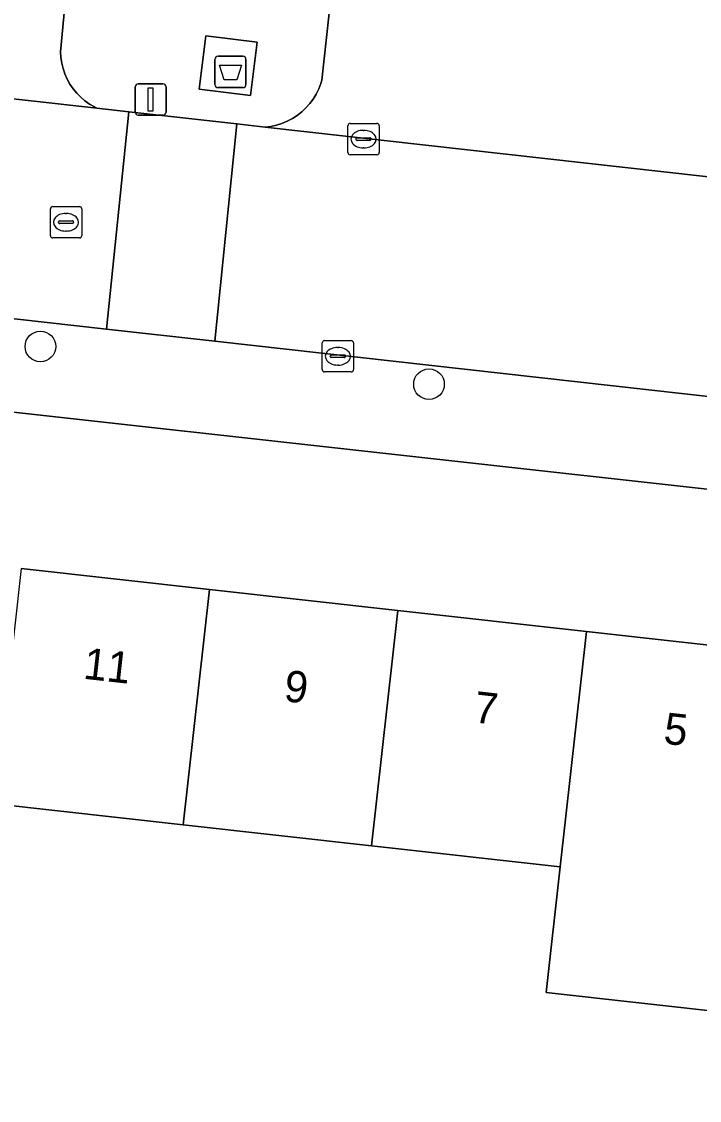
# Model space of a CAD drawing. Extents: x 161928 to 163071, y 386474 to 387428.
# Drawn here: x 162343.49 to 162365.12, y 386624.08 to 386658.51 of the extents above; entities that cross this region are included whole.
import ezdxf

# ---------------------------------------------------------------- set-up
doc = ezdxf.new("R2010")
doc.units = 0
for name, color, linetype in [('IMGEO_Afval_apart_plaats', 7, 'Continuous'), ('IMGEO_Boom', 7, 'Continuous'), ('IMGEO_Erf', 7, 'Continuous'), ('IMGEO_Kolk', 7, 'Continuous'), ('IMGEO_Lichtmast', 7, 'Continuous'), ('IMGEO_Pand', 7, 'Continuous'), ('IMGEO_Pand_nummerreeks', 7, 'Continuous'), ('IMGEO_Parkeervlak_open', 7, 'Continuous'), ('IMGEO_Rijbaan_lokaal_open', 7, 'Continuous'), ('IMGEO_Rioolput', 7, 'Continuous'), ('IMGEO_Voetpad_gesloten', 7, 'Continuous'), ('IMGEO_Voetpad_open', 7, 'Continuous')]:
    doc.layers.add(name, color=color, linetype=linetype)

msp = doc.modelspace()

# ---------------------------------------------------------------- linework, layer by layer
at = {"layer": 'IMGEO_Afval_apart_plaats'}
for p, q in [((162349.765, 386657.407), (162350.555, 386657.407)), ((162350.555, 386657.407), (162349.765, 386657.407)), ((162349.665, 386656.507), (162349.665, 386657.307)), ((162349.665, 386657.307), (162349.665, 386656.507)), ((162350.655, 386657.307), (162350.655, 386656.507)), ((162350.655, 386656.507), (162350.655, 386657.307)), ((162350.555, 386656.407), (162349.765, 386656.407)), ((162349.765, 386656.407), (162350.555, 386656.407))]:
    msp.add_line(p, q, dxfattribs=at)
msp.add_lwpolyline([(162349.808, 386657.121), (162350.512, 386657.121), (162350.363, 386656.651), (162349.957, 386656.651), (162349.808, 386657.121)], dxfattribs=at)
for centre, start, end in [((162349.765, 386657.307), 90, 180), ((162349.765, 386657.307), 90, 180), ((162350.555, 386657.307), 0, 90), ((162350.555, 386657.307), 360, 90), ((162349.765, 386656.507), 180, 270), ((162349.765, 386656.507), 180, 270), ((162350.555, 386656.507), 270, 0), ((162350.555, 386656.507), 270, 0)]:
    msp.add_arc(centre, 0.1, start, end, dxfattribs=at)
at = {"layer": 'IMGEO_Boom'}
for centre in [(162344.095, 386648.145), (162356.495, 386646.941)]:
    msp.add_circle(centre, 0.489, dxfattribs=at)
at = {"layer": 'IMGEO_Erf'}
for points in [[(162380.485, 386616.728), (162382.904, 386638.649), (162382.921, 386638.915), (162382.915, 386639.182), (162382.885, 386639.447), (162382.831, 386639.709), (162382.754, 386639.964), (162382.654, 386640.212), (162382.533, 386640.45), (162382.391, 386640.676), (162382.229, 386640.888), (162382.049, 386641.085), (162381.852, 386641.266), (162381.64, 386641.427), (162381.414, 386641.57), (162381.177, 386641.691), (162380.929, 386641.791), (162380.674, 386641.869), (162380.412, 386641.923), (162215.989, 386660.188)], [(162343.479, 386641.063), (162349.492, 386640.391), (162355.505, 386639.719), (162361.517, 386639.048), (162367.53, 386638.376), (162373.542, 386637.704), (162379.735, 386637.012), (162378.895, 386629.497), (162373.926, 386630.052), (162372.702, 386630.186), (162366.69, 386630.859), (162366.243, 386626.856), (162360.23, 386627.527), (162360.677, 386631.533), (162354.665, 386632.205), (162348.652, 386632.877), (162342.639, 386633.548)]]:
    msp.add_lwpolyline(points, dxfattribs=at)
at = {"layer": 'IMGEO_Kolk'}
for p, q in [((162353.981, 386655.263), (162354.833, 386655.263)), ((162353.906, 386654.337), (162353.906, 386655.189)), ((162354.394, 386655.043), (162354.419, 386655.043)), ((162354.907, 386655.189), (162354.907, 386654.337)), ((162354.165, 386654.757), (162354.165, 386654.769)), ((162354.603, 386654.72), (162354.205, 386654.72)), ((162354.208, 386654.806), (162354.606, 386654.806)), ((162354.649, 386654.769), (162354.649, 386654.757)), ((162354.833, 386654.263), (162353.981, 386654.263)), ((162354.417, 386654.483), (162354.392, 386654.483)), ((162353.087, 386647.405), (162353.087, 386648.257)), ((162353.162, 386648.331), (162354.014, 386648.331)), ((162353.575, 386648.111), (162353.6, 386648.111)), ((162354.088, 386648.257), (162354.088, 386647.405)), ((162353.346, 386647.825), (162353.346, 386647.837)), ((162353.784, 386647.788), (162353.386, 386647.788)), ((162353.389, 386647.874), (162353.787, 386647.874)), ((162353.83, 386647.837), (162353.83, 386647.825)), ((162353.598, 386647.551), (162353.573, 386647.551)), ((162354.014, 386647.331), (162353.162, 386647.331))]:
    msp.add_line(p, q, dxfattribs=at)
for points in [[(162353.981, 386655.263), (162354.833, 386655.263)], [(162353.906, 386654.337), (162353.906, 386655.189)], [(162354.907, 386655.189), (162354.907, 386654.337)], [(162354.833, 386654.263), (162353.981, 386654.263)], [(162353.087, 386647.405), (162353.087, 386648.257)], [(162353.162, 386648.331), (162354.014, 386648.331)], [(162354.088, 386648.257), (162354.088, 386647.405)], [(162354.014, 386647.331), (162353.162, 386647.331)]]:
    msp.add_lwpolyline(points, dxfattribs=at)
for centre, radius, start, end in [((162353.983, 386655.187), 0.0765, 91.552, 178.448), ((162353.983, 386655.187), 0.0765, 91.552, 178.448), ((162354.831, 386655.187), 0.0765, 1.552, 88.448), ((162354.831, 386655.187), 0.0765, 1.552, 88.448), ((162354.205, 386654.766), 0.0403, 85.8775, 175.7526), ((162354.202, 386654.756), 0.0366, 178.938, 274.7102), ((162354.606, 386654.763), 0.043, 264.8664, 352.4533), ((162354.61, 386654.768), 0.0386, 1.7309, 96.639), ((162353.983, 386654.339), 0.0765, 181.552, 268.448), ((162353.983, 386654.339), 0.0765, 181.552, 268.448), ((162354.831, 386654.339), 0.0765, 271.552, 358.448), ((162354.831, 386654.339), 0.0765, 271.552, 358.448), ((162353.164, 386648.255), 0.0765, 91.552, 178.448), ((162353.164, 386648.255), 0.0765, 91.552, 178.448), ((162354.012, 386648.255), 0.0765, 1.552, 88.448), ((162354.012, 386648.255), 0.0765, 1.552, 88.448), ((162353.386, 386647.834), 0.0403, 85.8775, 175.7526), ((162353.383, 386647.824), 0.0366, 178.938, 274.7102), ((162353.787, 386647.831), 0.043, 264.8664, 352.4533), ((162353.791, 386647.836), 0.0386, 1.7309, 96.639), ((162353.164, 386647.407), 0.0765, 181.552, 268.448), ((162353.164, 386647.407), 0.0765, 181.552, 268.448), ((162354.012, 386647.407), 0.0765, 271.552, 358.448), ((162354.012, 386647.407), 0.0765, 271.552, 358.448)]:
    msp.add_arc(centre, radius, start, end, dxfattribs=at)
for centre, major_axis, ratio, start_param, end_param in [((162354.393, 386654.763), (-0.387, 0.002), 0.722429, 4.712389, 7.853982), ((162354.418, 386654.763), (-0.39, 0.002), 0.717154, 1.570796, 4.712389), ((162353.574, 386647.831), (-0.387, 0.002), 0.722429, 4.712389, 7.853982), ((162353.599, 386647.831), (-0.39, 0.002), 0.717154, 1.570796, 4.712389)]:
    msp.add_ellipse(centre, major_axis=major_axis, ratio=ratio, start_param=start_param, end_param=end_param, dxfattribs=at)
at = {"layer": 'IMGEO_Lichtmast'}
for p, q in [((162347.117, 386655.628), (162347.117, 386656.428)), ((162347.117, 386656.428), (162347.117, 386655.628)), ((162347.217, 386656.528), (162348.007, 386656.528)), ((162348.007, 386656.528), (162347.217, 386656.528)), ((162348.107, 386656.428), (162348.107, 386655.628)), ((162348.107, 386655.628), (162348.107, 386656.428)), ((162348.007, 386655.528), (162347.217, 386655.528)), ((162347.217, 386655.528), (162348.007, 386655.528))]:
    msp.add_line(p, q, dxfattribs=at)
msp.add_lwpolyline([(162347.537, 386656.403), (162347.687, 386656.403), (162347.687, 386655.653), (162347.537, 386655.653), (162347.537, 386656.403)], dxfattribs=at)
for centre, start, end in [((162347.217, 386656.428), 90, 180), ((162347.217, 386656.428), 90, 180), ((162348.007, 386656.428), 0, 90), ((162348.007, 386656.428), 360, 90), ((162347.217, 386655.628), 180, 270), ((162347.217, 386655.628), 180, 270), ((162348.007, 386655.628), 270, 0), ((162348.007, 386655.628), 270, 0)]:
    msp.add_arc(centre, 0.1, start, end, dxfattribs=at)
at = {"layer": 'IMGEO_Pand'}
for points in [[(162349.492, 386640.391), (162343.479, 386641.063), (162342.639, 386633.548), (162348.652, 386632.877)], [(162348.652, 386632.877), (162354.665, 386632.205), (162355.505, 386639.719), (162349.492, 386640.391)], [(162354.665, 386632.205), (162360.677, 386631.533), (162361.517, 386639.048), (162355.505, 386639.719)], [(162367.53, 386638.376), (162361.517, 386639.048), (162360.677, 386631.533), (162360.23, 386627.527), (162366.243, 386626.856), (162366.69, 386630.859)]]:
    msp.add_lwpolyline(points, close=True, dxfattribs=at)
at = {"layer": 'IMGEO_Parkeervlak_open'}
for points in [[(162308.731, 386659.914), (162345.899, 386655.749), (162345.821, 386655.788), (162345.665, 386655.879), (162345.517, 386655.983), (162345.38, 386656.101), (162345.253, 386656.23), (162345.139, 386656.37), (162345.037, 386656.52), (162344.949, 386656.678), (162344.876, 386656.843), (162344.817, 386657.015), (162344.775, 386657.19), (162344.748, 386657.369), (162344.737, 386657.55), (162345.039, 386660.716)], [(162353.45, 386660.059), (162353.075, 386656.639), (162353.042, 386656.533), (162352.976, 386656.363), (162352.895, 386656.198), (162352.799, 386656.042), (162352.69, 386655.895), (162352.568, 386655.758), (162352.434, 386655.632), (162352.289, 386655.519), (162352.135, 386655.42), (162351.973, 386655.334), (162351.804, 386655.264), (162351.629, 386655.209), (162351.45, 386655.169), (162351.268, 386655.146), (162380.511, 386651.869)]]:
    msp.add_lwpolyline(points, dxfattribs=at)
at = {"layer": 'IMGEO_Rijbaan_lokaal_open'}
for points in [[(162308.731, 386659.914), (162302.86, 386660.57), (162265.999, 386664.701), (162264.937, 386664.82), (162264.197, 386657.891), (162266.476, 386657.636), (162275.101, 386656.669), (162323.439, 386651.25), (162332.841, 386650.196), (162346.203, 386648.698), (162346.919, 386655.634), (162345.899, 386655.749)], [(162349.66, 386648.311), (162350.363, 386655.248), (162346.919, 386655.634), (162346.203, 386648.698)]]:
    msp.add_lwpolyline(points, close=True, dxfattribs=at)
msp.add_lwpolyline([(162380.511, 386651.869), (162351.268, 386655.146), (162350.363, 386655.248), (162349.66, 386648.311), (162380.681, 386644.833)], dxfattribs=at)
at = {"layer": 'IMGEO_Rioolput'}
for p, q in [((162344.412, 386651.683), (162344.412, 386652.535)), ((162344.487, 386652.609), (162345.339, 386652.609)), ((162345.413, 386652.535), (162345.413, 386651.683)), ((162344.9, 386652.389), (162344.925, 386652.389)), ((162344.671, 386652.103), (162344.671, 386652.115)), ((162345.109, 386652.066), (162344.711, 386652.066)), ((162344.714, 386652.152), (162345.112, 386652.152)), ((162344.923, 386651.829), (162344.898, 386651.829)), ((162345.155, 386652.115), (162345.155, 386652.103)), ((162345.339, 386651.609), (162344.487, 386651.609))]:
    msp.add_line(p, q, dxfattribs=at)
for points in [[(162344.412, 386651.683), (162344.412, 386652.535)], [(162344.487, 386652.609), (162345.339, 386652.609)], [(162345.413, 386652.535), (162345.413, 386651.683)], [(162345.339, 386651.609), (162344.487, 386651.609)]]:
    msp.add_lwpolyline(points, dxfattribs=at)
for centre, radius, start, end in [((162344.489, 386652.533), 0.0765, 91.552, 178.448), ((162344.489, 386652.533), 0.0765, 91.552, 178.448), ((162345.337, 386652.533), 0.0765, 1.552, 88.448), ((162345.337, 386652.533), 0.0765, 1.552, 88.448), ((162344.711, 386652.112), 0.0403, 85.8775, 175.7526), ((162344.708, 386652.102), 0.0366, 178.938, 274.7102), ((162345.112, 386652.109), 0.043, 264.8664, 352.4533), ((162345.116, 386652.114), 0.0386, 1.7309, 96.639), ((162344.489, 386651.685), 0.0765, 181.552, 268.448), ((162344.489, 386651.685), 0.0765, 181.552, 268.448), ((162345.337, 386651.685), 0.0765, 271.552, 358.448), ((162345.337, 386651.685), 0.0765, 271.552, 358.448)]:
    msp.add_arc(centre, radius, start, end, dxfattribs=at)
for centre, major_axis, ratio, start_param, end_param in [((162344.899, 386652.109), (-0.387, 0.002), 0.722429, 4.712389, 7.853982), ((162344.924, 386652.109), (-0.39, 0.002), 0.717154, 1.570796, 4.712389)]:
    msp.add_ellipse(centre, major_axis=major_axis, ratio=ratio, start_param=start_param, end_param=end_param, dxfattribs=at)
at = {"layer": 'IMGEO_Voetpad_gesloten'}
msp.add_lwpolyline([(162351.01, 386657.857), (162349.371, 386658.064), (162349.156, 386656.358), (162350.795, 386656.151)], close=True, dxfattribs=at)
at = {"layer": 'IMGEO_Voetpad_open'}
for points in [[(162345.039, 386660.716), (162344.737, 386657.55), (162344.748, 386657.369), (162344.775, 386657.19), (162344.817, 386657.015), (162344.876, 386656.843), (162344.949, 386656.678), (162345.037, 386656.52), (162345.139, 386656.37), (162345.253, 386656.23), (162345.38, 386656.101), (162345.517, 386655.983), (162345.665, 386655.879), (162345.821, 386655.788), (162345.899, 386655.749), (162346.919, 386655.634), (162350.363, 386655.248), (162351.268, 386655.146), (162351.45, 386655.169), (162351.629, 386655.209), (162351.804, 386655.264), (162351.973, 386655.334), (162352.135, 386655.42), (162352.289, 386655.519), (162352.434, 386655.632), (162352.568, 386655.758), (162352.69, 386655.895), (162352.799, 386656.042), (162352.895, 386656.198), (162352.976, 386656.363), (162353.042, 386656.533), (162353.075, 386656.639), (162353.45, 386660.059)], [(162215.989, 386660.188), (162380.412, 386641.923), (162385.435, 386641.384), (162385.194, 386641.858), (162384.912, 386642.308), (162384.591, 386642.731), (162384.233, 386643.123), (162383.842, 386643.482), (162383.42, 386643.805), (162382.971, 386644.088), (162382.498, 386644.331), (162382.006, 386644.53), (162381.498, 386644.684), (162380.978, 386644.793), (162380.681, 386644.833), (162349.66, 386648.311), (162346.203, 386648.698), (162332.841, 386650.196)]]:
    msp.add_lwpolyline(points, dxfattribs=at)
msp.add_lwpolyline([(162350.795, 386656.151), (162349.156, 386656.358), (162349.371, 386658.064), (162351.01, 386657.857)], close=True, dxfattribs=at)

# ---------------------------------------------------------------- texts
at = {"layer": 'IMGEO_Pand_nummerreeks'}
for s, rotation, p in [('11', 353.6243, (162345.436, 386637.545)), ('9', 353.6243, (162351.838, 386636.829)), ('7', 353.6243, (162357.895, 386636.152)), ('5', 353.623, (162363.953, 386635.475))]:
    msp.add_text(s, height=1, rotation=rotation, dxfattribs=at).set_placement(p)

doc.saveas('drawing.dxf')
